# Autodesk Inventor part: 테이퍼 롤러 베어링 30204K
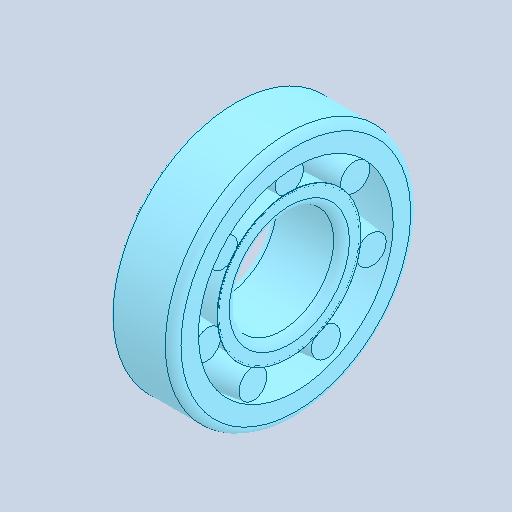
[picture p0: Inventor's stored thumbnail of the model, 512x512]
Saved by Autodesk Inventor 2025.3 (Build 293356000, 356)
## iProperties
Created: 2026-01
Part Number: 테이퍼 롤러 베어링 30204K
Material: 강철, 연강
Description: 테이퍼 롤러 베어링
Document SubType Name: Modeling
Designer: PC-13
Density: 7.85 g/cm^3
Appearance: 기본값
Author: jhkim
Sending System: Autodesk Inventor 2026
Preprocessor: ST-DEVELOPER v20.1
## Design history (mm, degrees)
feature "Solid1"
feature "Solid1:1"
node "솔리드1"
node "솔리드2"
